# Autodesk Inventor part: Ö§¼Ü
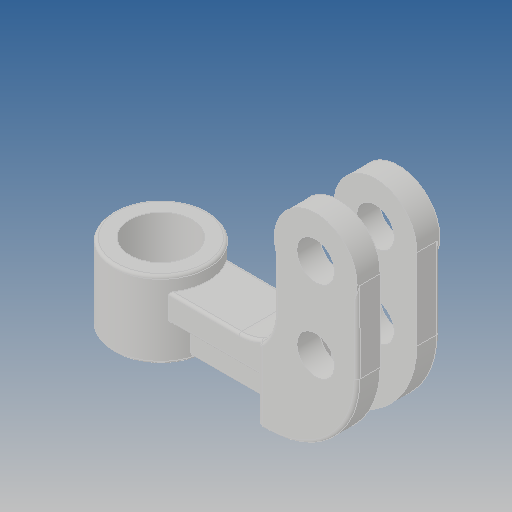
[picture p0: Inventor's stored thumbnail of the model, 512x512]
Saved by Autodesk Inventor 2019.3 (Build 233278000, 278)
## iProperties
Created: 2017-12
Part Number: Ö§¼Ü
Material: Ogólny
Document SubType Name: Modeling
Designer: Admin
Density: 1 g/cm^3
Appearance: Domyślna
Author: Admin
Revision Number: ÈÎºÎ
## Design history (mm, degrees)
feature "Ô²½Ç6"
node "Bryła1"
